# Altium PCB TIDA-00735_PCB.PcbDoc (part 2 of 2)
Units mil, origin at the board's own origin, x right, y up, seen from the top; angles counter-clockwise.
Board outline 1000 x 2200 mil, 2 copper layers (Top Layer, Bottom Layer), stack 62 mil thick; 69 components, 59 nets, 244 pads, 158 vias.
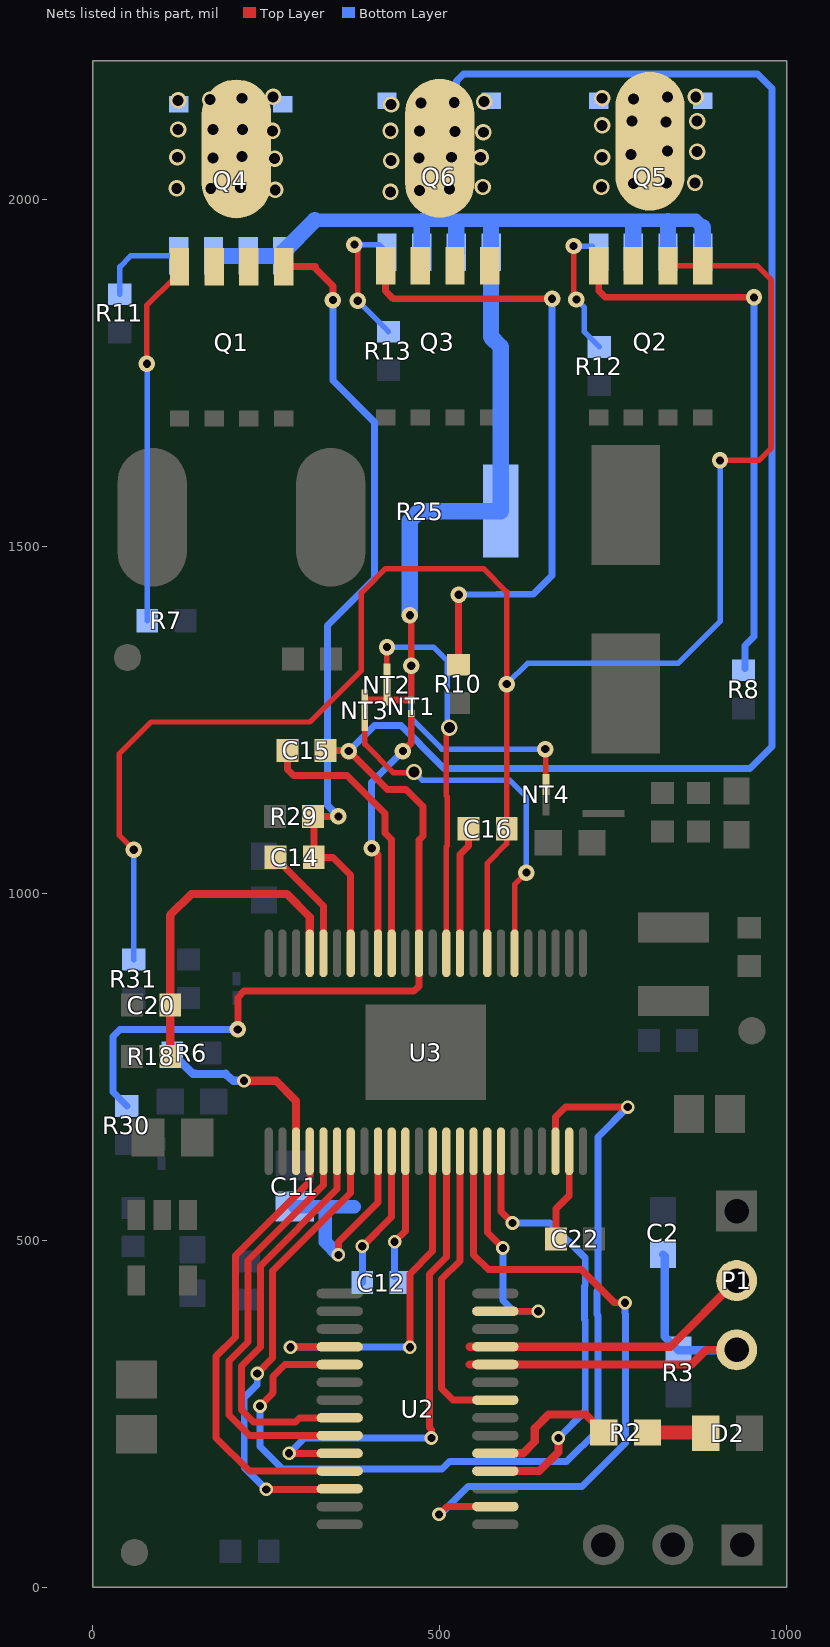
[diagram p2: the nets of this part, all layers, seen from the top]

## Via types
v1: diameter 23.62, hole 15.75, Top Layer to Bottom Layer, 62 vias
v2: diameter 19.68, hole 11.81, Top Layer to Bottom Layer, 55 vias
v3: diameter 23.62, hole 11.81, Top Layer to Bottom Layer, 26 vias
v4: diameter 19.68, hole 12, Top Layer to Bottom Layer, 8 vias
v5: diameter 23.62, hole 11.81, Top Layer to Bottom Layer, tented both sides, 6 vias
v6: diameter 19.68, hole 15.75, Top Layer to Bottom Layer, 1 vias

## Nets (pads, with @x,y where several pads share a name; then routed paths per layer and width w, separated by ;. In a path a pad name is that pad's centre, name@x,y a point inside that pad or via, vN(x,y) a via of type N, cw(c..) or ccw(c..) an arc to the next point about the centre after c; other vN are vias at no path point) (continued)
IB_FB: U2.5 U3.22 | length 1380
  Top Layer w10: v2(241,261) 259.28,279.28 259.28,280.41 259.72,280.84 259.72,303.72 276.98,320.98 U2.5@355.79,320.98 ; U3.22@667.01,628.28 667.01,678.01 681,692 v2(771,692)
  Bottom Layer w10: v2(241,261) 241,202.87 273.59,170.28 503.28,170.28 514,181 682.87,181 728,226.13 728,391.6 726.41,393.19 726.41,426.81 728,428.4 728,649 v2(771,692)
NetC11_1: C11.1 U3.9 | length 336.3
  Top Layer w10: v2(354,479) 354,497.31 411.1,554.41 U3.9@411.1,628.28
  Bottom Layer w19.68: C11.1@291,548.47 324,548.47 335,548.47 ; v2(354,479) 335,498 335,548.47 ; 377,548.47 335,548.47
NetC12_1: C12.1 U3.10 | length 206.8
  Top Layer w10: v2(388.44,491.44) 430.79,533.79 U3.10@430.79,628.28
  Bottom Layer w10: C12.1@388.44,439 v2(388.44,491.44)
NetC12_2: C12.2 U3.11 | length 187.1
  Top Layer w10: v2(435,498) 450.47,513.47 450.47,550.53 U3.11@450.47,628.28
  Bottom Layer w10: C12.2@435,447.56 v2(435,498)
NetC14_1: C14.1 U3.44 | length 166.8
  Top Layer w10: C14.1@263.44,1052 263.44,1050.92 332.36,982 U3.44@332.36,913.72
NetC15_1: C15.1 U3.39 | length 399.9
  Top Layer w10: C15.1@280.44,1206 280.44,1178.56 289,1170 366.44,1170 421.44,1115 421.44,1087 430.79,1077.65 U3.39@430.79,913.72
NetC16_1: C16.1 U3.34 | length 184.3
  Top Layer w10: U3.34@529.21,913.72 529.21,1056 541.44,1068.23 C16.1@541.44,1093
NetC22_1: C22.1 U3.23 | length 134.3
  Top Layer w10: C22.1@667.44,502 667.44,545.44 686.69,564.69 U3.23@686.69,628.28
NetD2_2: D2.2 R2.1 | length 84.4
  Top Layer w19.68: R2.1@799.5,223 882.5,223 D2.2@883.5,222
NetNT1_1: NT1.1 NT2.1 NT3.1 NT4.2 Q4.1 Q4.2 Q4.3 Q5.1 Q5.2 Q5.3 Q6.1 Q6.2 Q6.3 R25.2 | length 2164.9
  Top Layer w7.87: NT4.2@653,1157 v5@653,1208
  Top Layer w10: NT3.1@392,1279 NT1.1@459,1279 459,1399 v3(457,1401)
  Bottom Layer w7.87: v5(459,1328) 459,1252 503,1208 v5(652,1208)
  Bottom Layer w19.68: 320,1970 869,1970 879,1960
  Bottom Layer w23.62: Q4.3@174,1918.7 Q4.2@224,1918.7 Q4.1@274,1918.7 274,1924 320,1970 ; v3(457,1401) 457,1537 471,1551 R25.2@588.14,1551 588.14,1787.86 574,1802 Q6.1@574,1923.7 574,1965 ; Q6.3@474,1923.7 474,1969 ; Q6.2@524,1923.7 524,1966 ; Q5.3@779,1923.7 779,1965 ; Q5.2@829,1923.7 829,1969 ; Q5.1@879,1923.7 879,1960
NetQ1_4: Q1.4 R7.2 | length 516.3
  Top Layer w7.87: v3(78,1763.44) 78,1839 78,1847.72 115.28,1885 Q1.4@124,1885
  Bottom Layer w7.87: v3(78,1763.44) 78.44,1763 R7.2@78.44,1393
NetQ2_4: Q2.4 R8.2 | length 804.3
  Top Layer w9.65: Q2.4@729,1904.3 729,1869 739,1859 v3(953,1859)
  Bottom Layer w9.65: R8.2@940,1323.56 940,1357 953,1370 v3(953,1859)
NetQ3_4: Q3.4 R10.2 | length 928.3
  Top Layer w10: Q3.4@422,1904.3 422,1868 433,1857 v3(662,1857) ; R10.2@527.37,1327.63 v3(527.37,1430.37)
  Bottom Layer w10: v3(527.37,1430.37) 635.37,1431.37 662,1458 v3(662,1857)
NetQ4_4: Q4.4 R11.2 | length 130.9
  Bottom Layer w7.87: R11.2@39,1863.56 39,1903 54.7,1918.7 Q4.4@124,1918.7
NetQ5_4: Q5.4 R12.2 | length 187.5
  Top Layer w7.87: v5(693,1933) 693,1860 v5(697,1856)
  Bottom Layer w7.87: v5(693,1933) Q5.4@719.7,1933 ; v5(697,1856) 708,1845 708,1809.56 R12.2@730,1787.56
NetQ6_4: Q6.4 R13.2 | length 215.4
  Top Layer w7.87: v5(377,1935) 382,1930 v5(382,1854)
  Bottom Layer w7.87: v5@377,1850 377,1854 377,1858.56 R13.2@426,1809.56 ; v5(377,1935) 412.7,1935 Q6.4@424,1923.7 Q6.4@426,1921.7
NetR2_2: R2.2 U2.19 | length 210.4
  Top Layer w11.81: U2.19@580.2,193.02 U2.19@596,193.02 ; U2.19@605,193.02 U2.19@596,193.02 ; R2.2@736.5,223 710.5,249 657,249 636.99,228.99 636.99,210.01 620,193.02 U2.19@596,193.02
NetR6_2: R6.2 U3.3 | length 280.3
  Top Layer w11.81: v2(218,730) 264,730 292.99,701.01 U3.3@292.99,628.28
  Bottom Layer w11.81: R6.2@114.44,770 144.44,740 147.59,740 148.1,739.49 191.01,739.49 191.53,740 199.05,732.48 199.89,732.48 202.37,730 v2(218,730)
PWM_AH: U2.4 U3.13 | length 538.9
  Top Layer w10: v2(285,346) 355.23,346 U2.4@355.79,346.57 ; v2(457,346) 457,451.57 489.84,484.41 U3.13@489.84,628.28
  Bottom Layer w10: v2(285,346) v2(457,346)
PWM_AL: U2.10 U3.14 | length 711.6
  Top Layer w10: v2(283,193) U2.10@355.79,193.02 ; v2(488,215) 488,227 485,230 485,451.47 509.53,476 U3.14@509.53,628.28
  Bottom Layer w10: v2(283,193) 305,215 v2(488,215)
PWM_BH: U2.22 U3.15 | length 437.2
  Top Layer w10: U3.15@529.21,628.28 529.21,470.34 502.87,444 502.87,286.13 519.2,269.8 U2.22@580.2,269.8
PWM_BL: U2.16 U3.16 | length 996.2
  Top Layer w10: v2(499,105) 510.25,116.25 U2.16@580.2,116.25 U2.16@579.95,116 ; U3.16@548.9,628.28 548.9,479.1 570,458 704,458 752,410 v2(767,410)
  Bottom Layer w10: v2(499,105) 500.75,105 541,145.25 705.25,145.25 768,208 768,394 767,395 v2(767,410)
PWM_CH: U2.27 U3.17 | length 343.7
  Top Layer w10: U3.17@568.58,628.28 568.58,511.42 v2(591,489) ; U2.27@580.2,397.75 v2(642,397.75)
  Bottom Layer w10: v2(591,489) 591,413 606.25,397.75 v2(642,397.75)
PWM_CL: U2.18 U3.18 | length 634.6
  Top Layer w10: U3.18@588.27,628.28 588.27,541.73 v2(605,525)
  Top Layer w11.81: U2.18@580.2,167.43 643.43,167.43 671,195 v2(671,215)
  Bottom Layer w10: v2(605,525) 659,525 709.78,474.22 709.78,435.46 708.54,434.22 708.54,385.78 709.78,384.54 709.78,253.78 v2(671,215)
SBWTCK: P1.2 U2.25 | length 424.3
  Top Layer w11.81: 543.2,346.57 832.57,346.57 P1.2@928,442
SBWTDIO: C2.1 P1.3 R3.1 U2.24 | length 650.1
  Top Layer w11.81: 543.2,320.98 863,320.98 884.02,342 P1.3@928,342
  Bottom Layer w11.81: C2.1@822,479.5 824.26,477.24 824.26,361.24 R3.1@844,341.5 893,341.5 ; 867,341.5 893,341.5 ; P1.3@927.5,341.5 893,341.5
SCLK: U2.12 U3.7 | length 670.1
  Top Layer w10: v2(237,308) 259.28,330.28 259.28,455.77 371.73,568.22 U3.7@371.73,628.28 ; v2(250,141) 354.95,141 U2.12@355.79,141.84
  Bottom Layer w10: v2(237,308) 237,292 218.28,273.28 218.28,172.72 v2(250,141)
SCS: U2.11 U3.4 | length 683.5
  Top Layer w10: U3.4@312.68,628.28 312.68,585 205.66,477.98 205.66,360.72 177.8,332.86 177.8,215.2 225.57,167.43 302,167.43 ; 318.79,167.43 302,167.43 ; U2.11@355.79,167.43 302,167.43
SDI: U2.9 U3.5 | length 631.8
  Top Layer w10: 318.79,218.61 295,218.61 ; U3.5@332.36,628.28 332.36,579.41 223.53,470.58 223.53,353.32 196.41,326.19 196.41,248.19 225.98,218.61 295,218.61 ; U2.9@355.79,218.61 295,218.61
SDO: U2.8 U3.6 | length 601.7
  Top Layer w10: 318.79,244.21 298,244.21 ; U3.6@352.05,628.28 352.05,573.82 241.41,463.18 241.41,345.91 214.28,318.79 214.28,255.59 231.59,238.28 292.08,238.28 298,244.21 ; U2.8@355.79,244.21 298,244.21
SH_A: C14.2 pad.2 Q1.1 Q1.2 Q1.3 Q4.5 Q4.6 Q4.7 Q4.8 R29.2 U3.42 | length 1182.5
  Top Layer w10: Q1.1@274,1903.3 317.98,1903.3 ; 320.7,1903.3 317.98,1903.3 ; v3(346,1855) 346,1875.28 317.98,1903.3 ; v3(354,1111) R29.2@317.56,1111 318.56,1110 C14.2@318.56,1052 346,1052 371.73,1026.27 U3.42@371.73,913.72
  Bottom Layer w10: v3(346,1855) 346,1739 406,1679 406,1454 338,1386 338,1127 v3(354,1111)
  other v1: 263,2014 121,2016 170,2016 213,2017 262,2059 173,2060 122,2061 215,2062 259,2099 123,2101 173,2101 216,2101 123,2143 169,2144 215,2146 260,2148
SH_B: C15.2 pad.3 Q3.1 Q3.2 Q3.3 Q6.5 Q6.6 Q6.7 Q6.8 R30.2 U3.37 | length 3150.8
  Top Layer w10: v3(209,804) 209,850 218,859 463,859 470.16,866.16 U3.37@470.16,913.72 470.16,1077.16 476,1083 476,1125 451.5,1149.5 424.5,1149.5 v3(369,1205) ; C15.2@335.56,1206 v3@369,1206
  Bottom Layer w10: R30.2@49,693.56 29,713.56 29,794 39,804 v3(209,804) ; v3(369,1205) 406,1242 444.09,1242 456.4,1229.69 457.22,1229.69 471.68,1215.23 471.68,1214.4 506.09,1180 947,1180 979,1212 979,2160 958,2181 534,2181 524,2171 Q6.7@524,2142.3
  other v1: 429,2011 471,2013 514,2015 562,2018 430,2056 470,2060 517,2061 559,2061 563,2097 522,2098 429,2099 471,2099 430,2137 473,2139 521,2140 564,2141
SH_C: C16.2 pad.4 Q2.1 Q2.2 Q2.3 Q5.5 Q5.6 Q5.7 Q5.8 R31.2 U3.32 | length 2643.9
  Top Layer w7.87: v3(59,1063) 38,1084 38,1201 84,1247 313,1247 387,1321 387,1433 422,1468 563,1468 596.56,1434.44 v3(596.56,1301.56) C16.2@596.56,1093 596.56,1071.56 568.58,1043.58 U3.32@568.58,913.72 ; Q2.2@829,1904.3 Q2.1@879,1904.3 957.7,1904.3 978,1884 978,1642 960,1624 v3(904,1624)
  Bottom Layer w7.87: R31.2@59,904.56 v3(59,1063) ; v3(596.56,1301.56) 627,1332 844,1332 904,1392 v3(904,1624)
  other v1: 733,2018 779,2023 827,2024 868,2024 734,2061 776,2065 871,2069 828,2070 734,2107 826,2112 777,2113 871,2113 779,2145 734,2146 828,2148 869,2148
SL_A: NT1.2 U3.40 | length 372.7
  Top Layer w10: v3(402,1065) 411.1,1055.9 U3.40@411.1,913.72 ; v3(447,1205) 459,1217 NT1.2@459,1259
  Bottom Layer w10: v3(402,1065) 402,1160 v3(447,1205)
SL_B: NT2.2 U3.35 | length 562.6
  Top Layer w7.87: NT2.2@424,1316 v3(424,1355) ; U3.35@509.53,913.72 509.53,1067.48 510.68,1068.63 510.68,1139.37 509.53,1140.52 509.53,1236.53 512,1239 v1(514,1239)
  Bottom Layer w7.87: v3(424,1355) 491,1355 511,1335 v1@511,1241 ; v1@514,1234 v1(514,1239)
SL_C: NT3.2 U3.30 | length 532.2
  Top Layer w7.87: NT3.2@392,1249 392,1215 433,1174 v1@464,1174 ; U3.30@607.95,913.72 607.95,1012.95 v3(625,1030)
  Bottom Layer w7.87: v1(463,1175) 475,1163 601,1163 625,1139 v3(625,1030)
VDD_SPI: C20.1 R18.1 U3.45 | length 483.2
  Top Layer w11.81: R18.1@111.56,765 C20.1@111.56,839 111.56,968.56 142,999 279.68,999 312.68,966 U3.45@312.68,913.72
pads on no net: FID1.1 FID2.1 FID3.1 U1.3 U1.4 U2.15 U2.20 U2.21 U2.26

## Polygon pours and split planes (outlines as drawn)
no net on Top Layer "Bottom Layer-No Net" (solid, remove dead copper, shelved, pour order 1001): 0,0 1000,0 1000,2200 0,2200 0,0
GND on Top Layer "Top Layer-No Net" (solid, remove dead copper, pour order 10): 0,0 1000,0 1000,2200 0,2200
GND on Bottom Layer "Bottom Layer-No Net" (hatched 90Degree grid 8 track 20, remove dead copper, pour order 1000): 0,0 1000,0 1000,2200 0,2200 0,0
NetNT1_1 on Bottom Layer "Bottom Layer-No Net" (solid, remove dead copper, pour order 6): 446.03,1870.91 446.03,1490.56 445,1489.47 450.17,1484 629.97,1484 629.97,1870.91 631,1872
NetNT1_1 on Bottom Layer "Bottom Layer-No Net" (solid, remove dead copper, pour order 4): 150,1979.74 150,1841 942,1841 946,1845.17 946,1986

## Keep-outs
Keep-Out Layer:
  the board outline again, w10

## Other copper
Top Layer:
  rectangle net SH_B: 458,1877 585,2156
  rectangle net SH_B: 411,1990 589,2173
  rectangle net SH_C: 720,1960 899,2176
  rectangle net SH_C: 770,1880 900,2003
  rectangle net SH_A: 110,1974 289,2175
  rectangle net SH_A: 161,1877 286,2011
  rectangle net +PVDD: 110,1670 888.98,1830
  rectangle net +PVDD: 718,1476 817,1705

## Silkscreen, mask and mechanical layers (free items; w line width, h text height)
Top Overlay:
  text "SH_B" at 418,1956 h31.5
  text "SH_A" at 49,1955 h31.5
  text "SH_C" at 729,1948 h31.5
  text "GND" at 196,1411 h39.37
  text "PVDD" at 20,1410 h39.37
  text "+" at 937,254 h31.5
  text "+" at 129,232 h31.5
  text ".PCB_Rev" at 452,23 h30
  text ".PRJ_Number" at 140,20 h30
Top Solder:
  rectangle: 120,1730 280,1826
  rectangle: 420,1730 580,1829.24
  rectangle: 720,1730 880,1830
M1 Board Outline:
  the board outline again, w10
M2 Board Dimensions:
  rectangle: 0,-275 125,-150
  rectangle: 125,-400 500,-275
  lines w7: 0,-275 1000,-275 ; 125,-400 125,-150 ; 250,-400 250,-150 ; 500,-400 500,-150 ; 750,-400 750,-150 ; 0,-400 1000,-400 1000,-150 0,-150 0,-400
M5 Assembly Top:
  lines w10: -292,-930.17 6308,-930.17 ; -292,-726.83 6310,-726.83 ; -292,-523.5 -292,-1133.5 3713,-1133.5 6310,-1133.5 6310,-523.5 -291.5,-523.5 -291.5,-1133.5 1284,-1133.5 ; 2173,-1133.5 2173,-523.5 ; 3440,-726.83 3440,-523.5 ; 4280,-726.83 4280,-523.5 ; 4902,-1140 4902,-937.17
  text "COMPONENTS MARKED 'DNP' SHOULD NOT BE POPULATED." at 1153.5,-318.5 h60
  text "ASSEMBLY VARIANT:" at 1153,-434 h60
  text ".VariantName" at 2189,-434 h60
  text "PCB VIEWED FROM TOP SIDE" at -228.5,-655.67 h60
  text "BOARD #:" at 2248,-655.67 h60
  text ".PRJ_Number" at 2793.5,-655.67 h60
  text "REV:" at 3638,-655.67 h60
  text ".PCB_Rev" at 3929.5,-655.67 h60
  text "SVN REV:" at 4476,-655.67 h60
  text ".VersionControl_RevNumber" at 4982,-655.67 h60
  text "TID #:" at 2248,-859 h60
  text ".TID" at 2793.5,-859 h60
  text "PLOT NAME =" at -228.5,-1064.34 h60
  text ".plot_File_Name" at 577,-1064.34 h60
  text "GENERATED    :" at 2250,-1064.34 h60
  text ".Print_Date" at 3119.5,-1064.34 h60
  text ".Print_Time" at 3848.5,-1064.34 h60
  text "TEXAS INSTRUMENTS" at 5113,-1064.34 h60
M6 Assembly Bottom:
  lines w10: -292.5,-727.33 6309.5,-727.33 ; -290.5,-930.67 6309.5,-930.67 ; 1115.5,-1140.5 1115.5,-937.67 ; 1737.5,-727.33 1737.5,-524 ; 2577.5,-727.33 2577.5,-524 ; 3844.5,-1134 3844.5,-524 ; 4733.5,-1134 6309,-1134 6309,-524 -292.5,-524 -292.5,-1134 2304.5,-1134 6309.5,-1134 6309.5,-524
  text "COMPONENTS MARKED 'DNP' SHOULD NOT BE POPULATED." at 6102,-318 h60
  text ".VariantName" at 5058,-434 h60
  text "ASSEMBLY VARIANT:" at 6097,-434 h60
  text ".VersionControl_RevNumber" at 1035.5,-656.17 h60
  text "SVN REV:" at 1541.5,-656.17 h60
  text ".PCB_Rev" at 2088,-656.17 h60
  text "REV:" at 2379.5,-656.17 h60
  text ".PRJ_Number" at 3224,-656.17 h60
  text "BOARD #:" at 3769.5,-656.17 h60
  text "PCB VIEWED FROM BOTTOM SIDE" at 6246,-656.17 h60
  text ".TID" at 3224,-859.5 h60
  text "TID #:" at 3769.5,-859.5 h60
  text "TEXAS INSTRUMENTS" at 904.5,-1064.84 h60
  text ".Print_Time" at 2169,-1064.84 h60
  text ".Print_Date" at 2898,-1064.84 h60
  text "GENERATED    :" at 3767.5,-1064.84 h60
  text ".plot_File_Name" at 5440.5,-1064.84 h60
  text "PLOT NAME =" at 6246,-1064.84 h60
M9 Title Sheet:
  drawing of 57 lines, arcs and shapes, not listed
  text "1" at 739.84,8036.5 h70
  text "2" at 3235.5,8036.5 h70
  text "3" at 5724.84,8036.5 h70
  text "4" at 8231.51,8036.5 h70
  text "5" at 10730.5,8036.5 h70
  text "6" at 13235.5,8036.5 h70
  text "A" at -416.5,6893.5 h70
  text "A" at 14383.5,6893.5 h70
  text "B" at -416.5,4513.5 h70
  text "B" at 14383.5,4513.5 h70
  text "C" at -416.5,2138.5 h70
  text "C" at 14383.5,2138.5 h70
  text "PROJECT TITLE:" at 11343.5,277.5 h45
  text ".PRJ_Title" at 11393.5,144.17 h70
  text "DESIGNED FOR:" at 11343.5,-23.5 h45
  text ".PRJ_Customer" at 11393.5,-163.5 h70
  text "D" at -416.5,-231.5 h70
  text "D" at 14383.5,-231.5 h70
  text "FILE NAME:" at 11343.5,-323.5 h45
  text ".PCB_File_Name_No_Path" at 11393.5,-443.5 h70
  text "Texas Instruments (TI) and/or its licensors do not warrant the accuracy or completeness of this specification" at 6374,-605.34 h45
  text "ENGINEER:" at 11343.5,-613.5 h45
  text "LAYOUT BY:" at 12848.5,-613.5 h45
  text "or any information contained therein. TI and/or its licensors do not warrant that this design will meet" at 6329.01,-718 h45
  text ".PRJ_Engineer" at 11393.5,-768.49 h70
  text ".PCB_Layout" at 12899,-768.49 h70
  text "the specifications, will be suitable for your application or fit for any particular purpose, or will operate in" at 6329.01,-830.67 h45
  text ".Layer_Name" at 577,-858.49 h60
  text "ALTIUM DESIGNER VERSION:" at 12848.5,-923.5 h45
  text "an implementation. TI and/or its licensors do not warrant that the design is production worthy. You should" at 6329.01,-943.33 h45
  text "completely validate and test your design implementation to confirm the system functionality for your application." at 6374,-1056 h45
  text ".print_Scale" at 11393.5,-1056.83 h70
  text ".Application_BuildNumber" at 12899,-1056.83 h70
  text "1" at 739.84,-1263.5 h70
  text "2" at 3235.5,-1263.5 h70
  text "3" at 5724.84,-1263.5 h70
  text "4" at 8231.51,-1263.5 h70
  text "5" at 10730.5,-1263.5 h70
  text "6" at 13235.5,-1263.5 h70
M10 Fab Notes:
  drawing of 189 lines, arcs and shapes, not listed
  text "DESIGN INFORMATION" at 12381.02,6028 h60
  text "MIN. TRACK WIDTH:" at 11736.46,5848 h60
  text "8" at 12832.7,5848 h60
  text "MIL" at 12987.46,5848 h60
  text "MIN. CLEARANCE:" at 11736.46,5716 h60
  text "0.2" at 12772.7,5716 h60
  text "mm" at 12987.46,5716 h60
  text "MIN. VIA PAD SIZE:" at 11736.46,5584 h60
  text "24" at 12802.71,5584 h60
  text "MIL" at 12987.46,5584 h60
  text "0.05mm (2MIL)" at 12431.46,5442.29 h60
  text "MINIMUM ANNULAR RING" at 11407.23,5438 h60
  text "EXTERNAL" at 13139.46,5438 h60
  text "PER" at 11607.23,5320 h60
  text "IPC-D-275 CLASS 2 LEVEL C" at 11827.23,5320 h60
  text "MIL, HOLES" at 13315.46,5207.71 h60
  text "+/-" at 12923,5207 h60
  text "+/-" at 13777,5207 h60
  text "REGISTRATION TOLERANCES:" at 11407.23,5202 h60
  text "METAL" at 12607,5202 h60
  text "5" at 13183.2,5202 h60
  text "3" at 14016.2,5202 h60
  text "MIL" at 14132.46,5202 h60
  text "+/-" at 13777,5089 h60
  text "HOLE SIZE TOLERANCE (UNLESS OTHERWISE SPECIFIED):" at 11407.23,5084 h60
  text "3" at 14016.2,5084 h60
  text "MIL" at 14132.46,5084 h60
  text "MATERIAL:" at 11332.46,4874.54 h60
  text "FR-4 High Tg" at 12318.9,4734.21 h60
  text "FR-408" at 11753.46,4725.64 h60
  text "OTHER" at 13241.46,4725.64 h60
  text "X" at 12164,4722 h60
  text "62 MIL (1.6mm) +/-10%" at 12073.56,4562.92 h60
  text "THICKNESS:" at 11407.23,4558.64 h60
  text "X" at 11945.4,4558.64 h60
  text "OTHER" at 13358.46,4558.64 h60
  text "TOLERANCE:" at 11407.23,4400.64 h60
  text "X" at 12246.53,4400.64 h60
  text "ANSI IPC-6012 TYPE 3 CLASS 2" at 12433.48,4400.64 h60
  text "OTHER +/-" at 12433.46,4244.64 h60
  text "BOW & TWIST:" at 11407.23,4087.64 h60
  text "X" at 12246.53,4087.64 h60
  text "ANSI IPC-6012 TYPE 3 CLASS 2" at 12433.48,4087.64 h60
  text "OTHER +/-" at 12433.46,3929.13 h60
  text "DRILLING:" at 11332.46,3790.64 h60
  text "REFERENCE:" at 11407.23,3673.64 h60
  text "X" at 12055.46,3673.64 h60
  text "AS SHOWN" at 12242.46,3673.64 h60
  text "X" at 12956.46,3673.64 h60
  text "NC_DRILL FILES" at 13093.46,3673.64 h60
  text "PTH MIN COPPER THICKNESS:" at 11407.23,3515.64 h60
  text "X" at 12757.46,3515.64 h60
  text "1MIL" at 12894.46,3515.64 h60
  text "OTHER" at 13391.46,3515.64 h60
  text "BOARD FINISH:" at 11332.46,3356.64 h60
  text "SILKSCREEN:" at 11487.68,3238.64 h60
  text "X" at 12436.46,3238.64 h60
  text "TOP" at 12562.46,3238.64 h60
  text "X" at 12946.46,3238.64 h60
  text "BOTTOM" at 13073.46,3238.64 h60
  text "SILKSCREEN COLOR:" at 11487.68,3071.64 h60
  text "X" at 12435.42,3071.64 h60
  text "WHITE" at 12562.46,3071.64 h60
  text "OTHER" at 13073.46,3071.64 h60
  text "X" at 12566.42,2912.44 h60
  text "GREEN" at 12693.46,2912.44 h60
  text "OTHER" at 13311.46,2912.44 h60
  text "SOLDER RESIST COLOR:" at 11487.68,2901.64 h60
  text "X" at 12566.42,2742.44 h60
  text "MATTE" at 12693.46,2742.44 h60
  text "SEMI-GLOSS" at 13311,2741.8 h60
  text "IMMERSION GOLD (ENIG)" at 12393.46,2553.92 h60
  text "ENEPIG" at 13731,2550.64 h60
  text "SURFACE FINISH:" at 11332.46,2549.64 h60
  text "X" at 12206.51,2549.64 h60
  text "IMM. TIN/SILVER OR EQUIV" at 11662,2392.64 h60
  text "OTHER" at 13093.46,2392.64 h60
  text "ARRAY/PANEL:" at 11332.46,2213.64 h60
  text "CUT AND TRIM PER M1 BOARD OUTLINE" at 12393.46,2209.35 h60
  text "N.C. ROUTE" at 12393.46,2057.64 h60
  text "X" at 13072.46,2057.64 h60
  text "V. SCORE" at 13259.46,2057.64 h60
  text "CERTIFICATION:" at 11332.46,1920.64 h60
  text "MATERIALS AND WORKMANSHIP FOR ALL PCBS" at 12057.46,1920.64 h60
  text "TO MEET OR EXCEED THE REQUIREMENTS OF:" at 12057.46,1822.64 h60
  text "X" at 11683.96,1686.13 h60
  text "ANSI IPC-A-600F CLASS ->" at 11822.96,1686.13 h60
  text "X" at 13462.02,1686.13 h60
  text "2" at 13580.96,1686.14 h60
  text "1" at 13265.96,1684.64 h60
  text "3" at 13934.96,1684.64 h60
  text "X" at 11686.02,1526.64 h60
  text "UL 94V-0" at 11822.96,1526.64 h60
  text "X" at 12498.02,1526.64 h60
  text "RoHS" at 12634.96,1526.64 h60
  text "OTHER" at 13279.36,1526.64 h60
  text "PER ORDER" at 13676.42,1526.64 h60
  text "ADDITIONAL REQUIREMENTS:" at 11332.46,1385.64 h60
  text "MICROSECTION:" at 11407.23,1270.64 h60
  text "YES" at 12312.96,1270.64 h60
  text "REQUIRED" at 13174.46,1114.49 h60
  text "BARE BOARD ELEC. TEST:" at 11407.23,1111.64 h60
  text "NONE" at 12712.96,1111.64 h60
  text "X" at 13047.46,1111.64 h60
  text "PER ORDER" at 13766.46,1111.64 h60
  text "MANUFACTURER'S UL:" at 11407.23,954.64 h60
  text "RAIL" at 12572.96,950.35 h60
  text "METAL" at 13064.77,950.35 h60
  text "X" at 13440,950 h60
  text "SILK" at 13576.46,950.35 h60
M11 Gerber Information:
  lines w10: -292,-930.17 6308,-930.17 ; -292,-726.83 6310,-726.83 ; -292,-523.5 -292,-1133.5 3713,-1133.5 6310,-1133.5 6310,-523.5 -291.5,-523.5 -291.5,-1133.5 1284,-1133.5 ; 2173,-1133.5 2173,-523.5 ; 3440,-726.83 3440,-523.5 ; 4280,-726.83 4280,-523.5 ; 4902,-1140 4902,-937.17
  text "ALL ARTWORK VIEWED FROM TOP SIDE" at -228.5,-655.67 h60
  text "BOARD #:" at 2248,-655.67 h60
  text ".PRJ_Number" at 2793.5,-655.67 h60
  text "REV:" at 3638,-655.67 h60
  text ".PCB_Rev" at 3929.5,-655.67 h60
  text "SVN REV:" at 4476,-655.67 h60
  text ".VersionControl_RevNumber" at 4982,-655.67 h60
  text "TID #:" at 2248,-859 h60
  text ".TID" at 2793.5,-859 h60
  text "PLOT NAME =" at -228.5,-1064.34 h60
  text ".plot_File_Name" at 577,-1064.34 h60
  text "GENERATED    :" at 2250,-1064.34 h60
  text ".Print_Date" at 3119.5,-1064.34 h60
  text ".Print_Time" at 3848.5,-1064.34 h60
  text "TEXAS INSTRUMENTS" at 5113,-1064.34 h60
M12 Stackup:
  drawing of 191 lines, arcs and shapes, not listed
  text "Layer" at 9790.58,7830 h60
  text "Name" at 10200.49,7830 h60
  text "Material" at 11130.23,7830 h60
  text "Thickness" at 11990,7830 h60
  text "Constant" at 12639.84,7830 h60
  text "Board Layer Stack" at 13209.7,7830 h60
  text "1" at 9790.58,7710 h60
  text "Top Overlay" at 10200.49,7710 h60
  text "2" at 9790.58,7590 h60
  text "Top Solder" at 10200.49,7590 h60
  text "Solder Resist" at 11130.23,7590 h60
  text "0.40mil" at 11990,7590 h60
  text "3.5" at 12639.84,7590 h60
  text "3" at 9790.58,7470 h60
  text "Top Layer" at 10200.49,7470 h60
  text "Copper" at 11130.23,7470 h60
  text "1.40mil" at 11990,7470 h60
  text "4" at 9790.58,7350 h60
  text "Dielectric1" at 10200.49,7350 h60
  text "FR-4" at 11130.23,7350 h60
  text "59.20mil" at 11990,7350 h60
  text "4.8" at 12639.84,7350 h60
  text "5" at 9790.58,7230 h60
  text "Bottom Layer" at 10200.49,7230 h60
  text "Copper" at 11130.23,7230 h60
  text "1.40mil" at 11990,7230 h60
  text "6" at 9790.58,7110 h60
  text "Bottom Solder" at 10200.49,7110 h60
  text "Solder Resist" at 11130.23,7110 h60
  text "0.40mil" at 11990,7110 h60
  text "3.5" at 12639.84,7110 h60
  text "7" at 9790.58,6990 h60
  text "Bottom Overlay" at 10200.49,6990 h60
Drill Drawing:
  circle w10: c5572.72,3221.04 r24.89
  lines w10: 5547.83,2748.2 5572.72,2760.64 5597.6,2748.2 5585.16,2773.08 5597.6,2797.97 5572.72,2785.53 5547.83,2797.97 5560.27,2773.08 5547.83,2748.2 ; 5547.83,2909.96 5560.27,2909.96 5572.72,2897.52 5585.16,2909.96 5597.6,2909.96 5585.16,2922.4 5597.6,2934.85 5585.16,2934.85 5572.72,2947.29 5560.27,2934.85 5547.83,2934.85 5560.27,2922.4 5547.83,2909.96 ; 5547.83,3096.61 5597.6,3096.61 5572.72,3046.84 5547.83,3096.61
  lines w12: 5480,2703.4 7598.02,2703.4 ; 5480,3300.68 7598.02,3300.68 ; 5850.36,2554.08 5850.36,3450 ; 6207.36,2554.08 6207.36,3450 ; 6868.93,2554.08 6868.93,3450 ; 7153.07,2554.08 7153.07,3450 ; 5480,2554.08 7598.02,2554.08 7598.02,3450 5480,3450 5480,2554.08
  text "Symbol" at 5569.59,3345.48 h72
  text "Quantity" at 5895.16,3345.48 h72
  text "Finished Hole Size" at 6252.16,3345.48 h72
  text "Plated" at 6913.72,3345.48 h72
  text "Hole Type" at 7197.86,3345.48 h72
  text "87" at 5895.16,3196.16 h60
  text "11.81mil (0.300mm)" at 6252.16,3196.16 h60
  text "PTH" at 6913.72,3196.16 h60
  text "Round" at 7197.86,3196.16 h60
  text "8" at 5895.16,3046.84 h60
  text "12.00mil (0.305mm)" at 6252.16,3046.84 h60
  text "PTH" at 6913.72,3046.84 h60
  text "Round" at 7197.86,3046.84 h60
  text "63" at 5895.16,2897.52 h60
  text "15.75mil (0.400mm)" at 6252.16,2897.52 h60
  text "PTH" at 6913.72,2897.52 h60
  text "Round" at 7197.86,2897.52 h60
  text "6" at 5895.16,2748.2 h60
  text "35.43mil (0.900mm)" at 6252.16,2748.2 h60
  text "PTH" at 6913.72,2748.2 h60
  text "Round" at 7197.86,2748.2 h60
  text "164 Total" at 5895.16,2598.88 h60

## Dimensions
0,-400 to 1000,-400 on M2 Board Dimensions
